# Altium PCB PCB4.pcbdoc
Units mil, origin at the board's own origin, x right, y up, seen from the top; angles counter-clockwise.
Board outline 10388.19 x 4173.23 mil, 4 copper layers (Top Layer, Inner1, Inner2, Bottom Layer); 12 components, 58 nets, 169 pads, 150 vias.
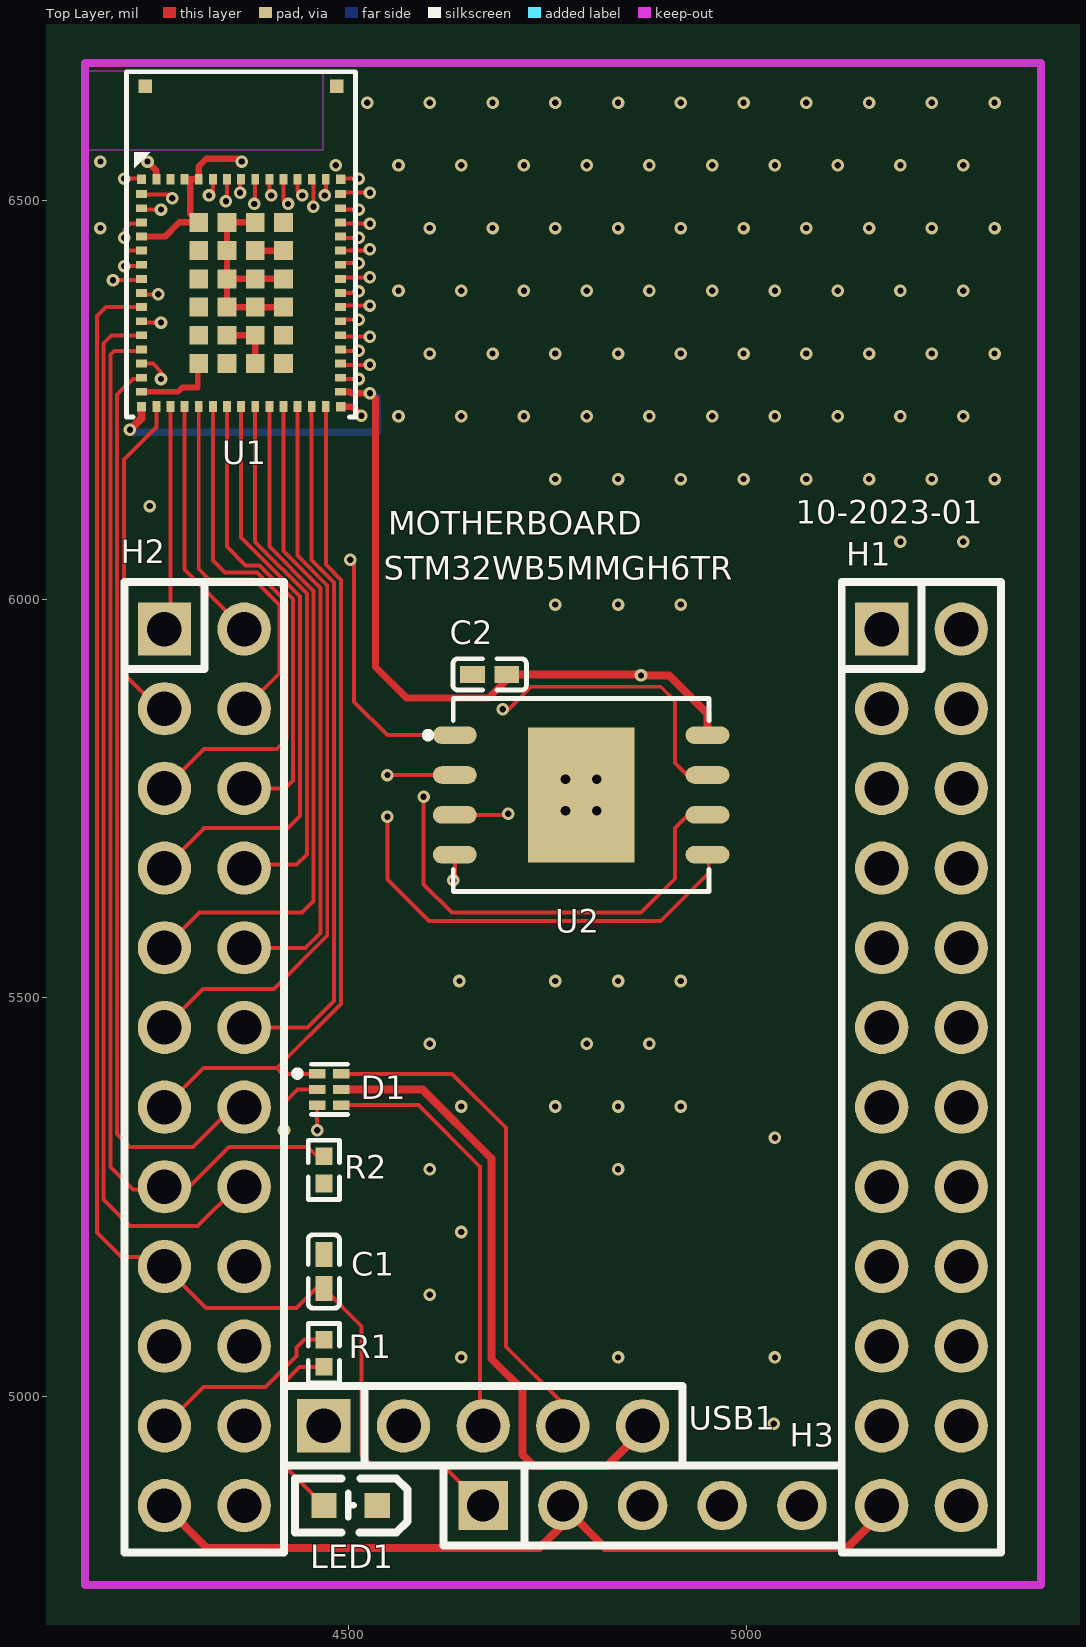
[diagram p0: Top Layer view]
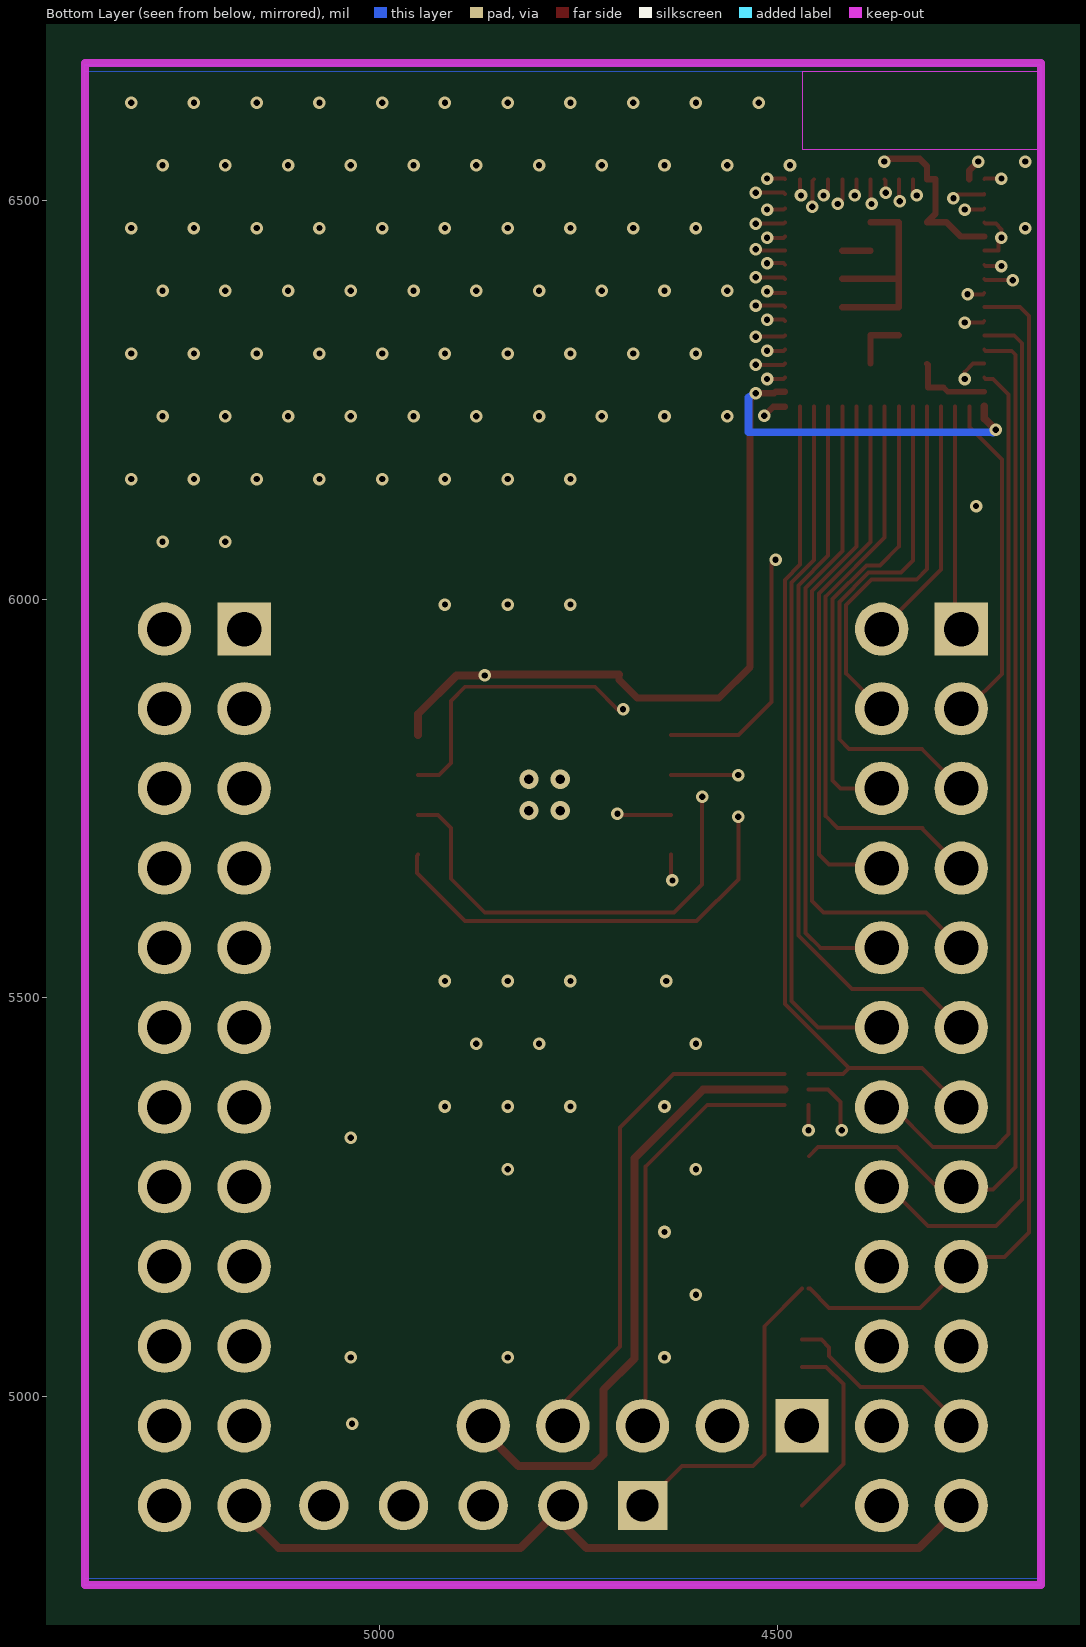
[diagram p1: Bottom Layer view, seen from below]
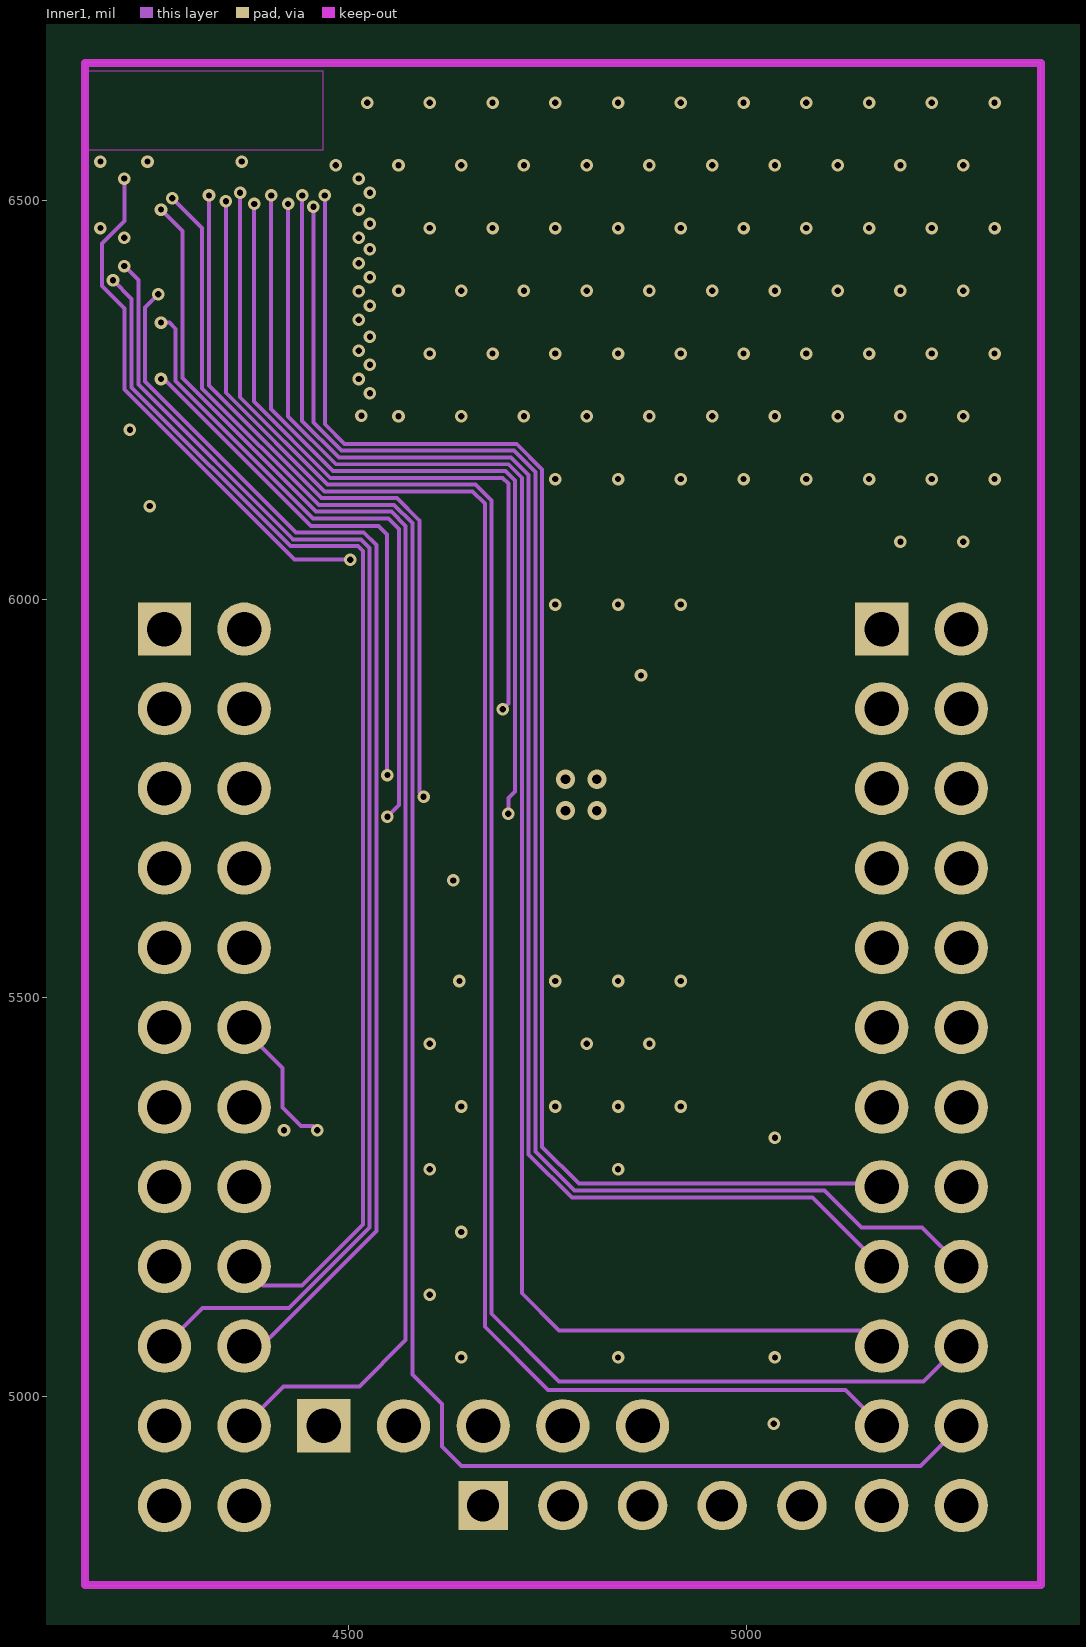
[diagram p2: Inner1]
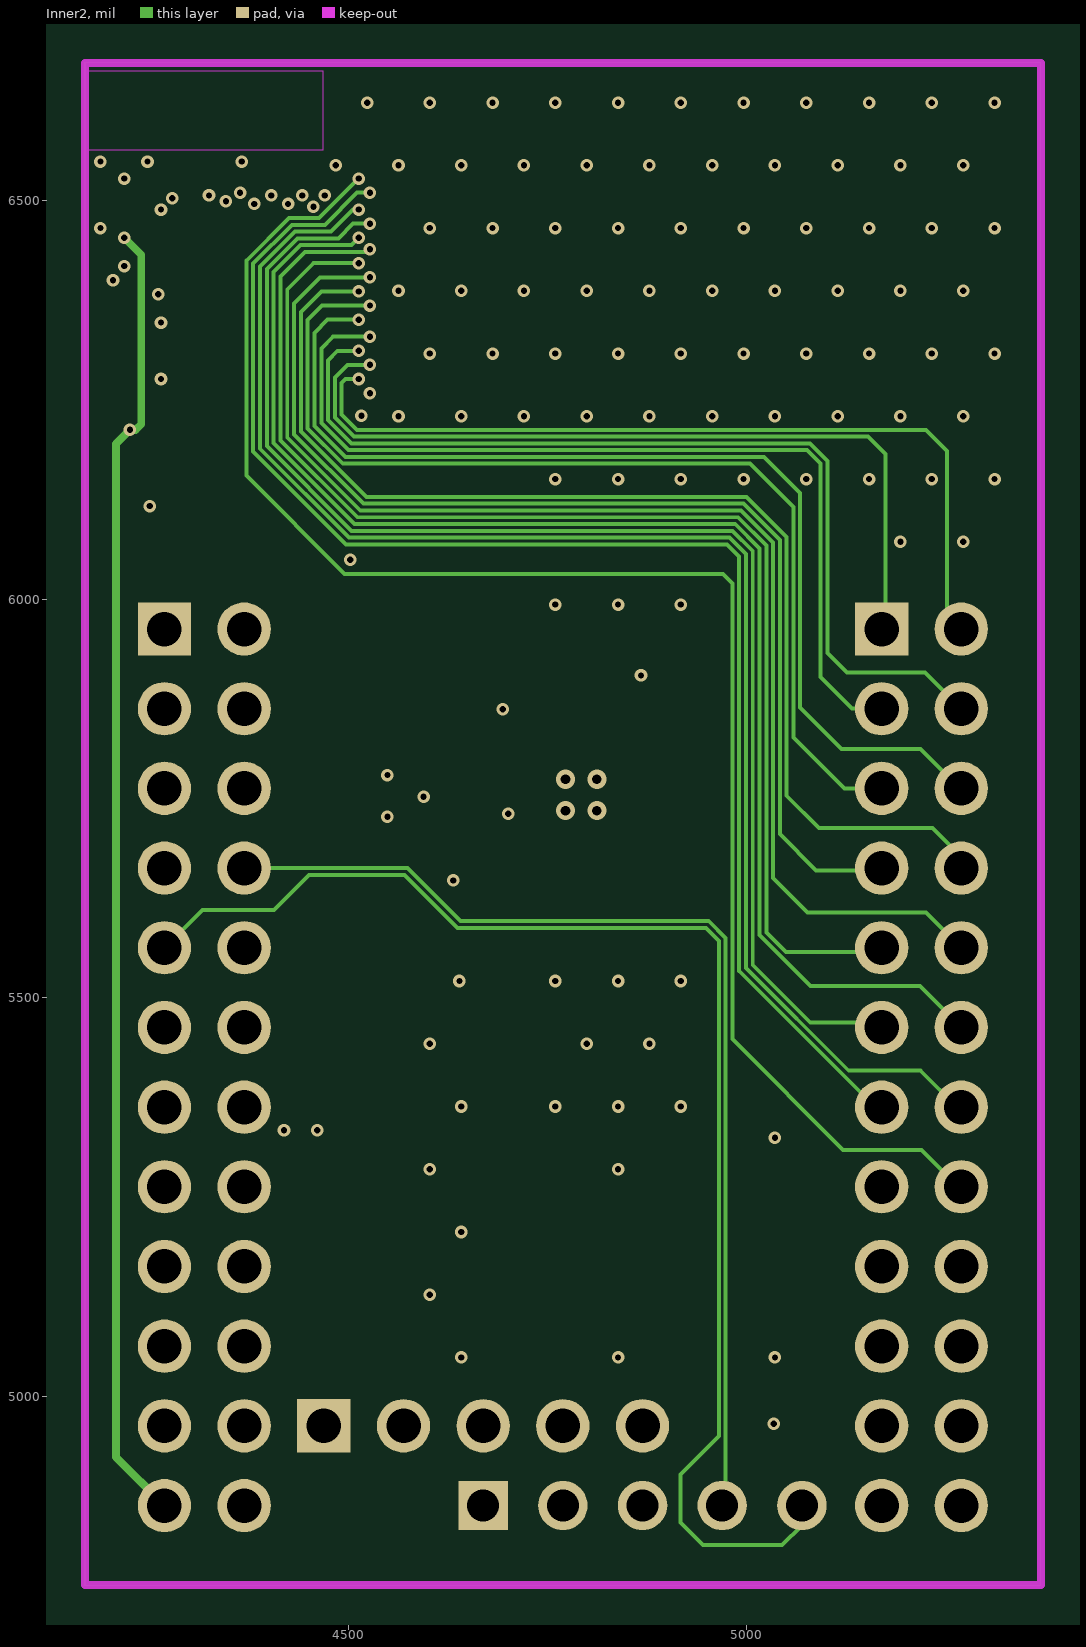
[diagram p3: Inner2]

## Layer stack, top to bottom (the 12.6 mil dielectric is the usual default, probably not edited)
Top Layer: signal copper (thickness not stored)
Dielectric: dielectric 12.6, FR-4, Dk 4.8
Inner1: signal copper (thickness not stored)
Dielectric: dielectric 12.6, FR-4, Dk 4.8
Inner2: signal copper (thickness not stored)
Dielectric: dielectric 12.6, FR-4, Dk 4.8
Bottom Layer: signal copper (thickness not stored)

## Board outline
13138.19,2750 2750,2750 2750,6923.23 13138.19,6923.23

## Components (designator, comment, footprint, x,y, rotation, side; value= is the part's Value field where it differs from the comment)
C1 "CL05B104KO5NNNC" C0402 4469.29,5156.3 r270 top
C2 "CL05B104KO5NNNC" C0402 4677.48,5905.69 r0 top
D1 "PRTR5V0U2F" SON-6_L1.5-W1.0-P0.50-BL 4476.17,5384.73 r270 top
H1 "PZ254-2-12-Z-8.5" HDR-TH_24P-P2.54-V-M-R2-C12-S2.54 5219.29,5412.6 r270 top
H2 "PZ254-2-12-Z-8.5" HDR-TH_24P-P2.54-V-M-R2-C12-S2.54 4319.29,5412.6 r270 top
H3 "HDR-F_2.54_1x5P" HDR-TH_5P-P2.54-V-F 4869.29,4862.6 r0 top
LED1 "19-217/R6C-AL1M2VY/3T" LED0603-R-RD 4502.79,4862.6 r180 top
R1 "0402WGJ0301TCE" R0402 4469.29,5053.73 r90 top
R2 "RC0402FR-0710KL" R0402 4469.29,5283.91 r90 top
U1 "STM32WB5MMGH6TR" LCC-LGA-86_L11.0-W7.3_STM32WB5MMGH6TR 4365.47,6442.6 r0 top
U2 "W25Q256JVEIQ_C97522" WSON-8_L8.0-W6.10-P1.27-BL-EP 4792.28,5754.38 r270 top
USB1 "HDR-M_2.54_1x5P" HDR-TH_5P-P2.54-V-M 4669.29,4962.6 r0 top

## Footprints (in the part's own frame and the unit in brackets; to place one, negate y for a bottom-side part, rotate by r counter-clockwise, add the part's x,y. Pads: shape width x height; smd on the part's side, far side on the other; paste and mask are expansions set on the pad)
C0402 [mm]
  rect 0.79x0.54 smd: 1(-0.545,0) 2(0.545,0)
  silkscreen extent -1.17,-0.5 1.17,0.5
HDR-TH_5P-P2.54-V-F [mil]
  rect 62x62 hole 40.16: 1(-200,0)
  round 62 hole 40.16: 2(-100,0) 3(0,0) 4(100,0) 5(200,0)
  silkscreen extent -250,-50 250,50
HDR-TH_5P-P2.54-V-M [mm]
  rect 1.7x1.7 hole 1.1: 1(-5.08,0)
  round 1.7 hole 1.1: 2(-2.54,0) 3(0,0) 4(2.54,0) 5(5.08,0)
  silkscreen extent -6.35,-1.27 6.35,1.27
HDR-TH_24P-P2.54-V-M-R2-C12-S2.54 [mm]
  rect 1.7x1.7 hole 1.1: 1(-13.97,-1.27)
  round 1.7 hole 1.1: 2(-13.97,1.27) 3(-11.43,-1.27) 4(-11.43,1.27) 5(-8.89,-1.27) 6(-8.89,1.27) 7(-6.35,-1.27) 8(-6.35,1.27) 9(-3.81,-1.27) 10(-3.81,1.27) 11(-1.27,-1.27) 12(-1.27,1.27) 13(1.27,-1.27) 14(1.27,1.27) 15(3.81,-1.27) 16(3.81,1.27) 17(6.35,-1.27) 18(6.35,1.27) 19(8.89,-1.27) 20(8.89,1.27) 21(11.43,-1.27) 22(11.43,1.27) 23(13.97,-1.27) 24(13.97,1.27)
  silkscreen extent -15.47,-2.54 15.47,2.54
LCC-LGA-86_L11.0-W7.3_STM32WB5MMGH6TR [mm]
  rect 0.3x0.3 smd: 1(-3.175,2.145) 17(-3.175,-5.105) 31(3.175,-5.105) 47(3.175,2.145)
  rect 0.35x0.25 smd: 2(-3.175,1.67) 3(-3.175,1.22) 4(-3.175,0.77) 5(-3.175,0.32) 6(-3.175,-0.13) 7(-3.175,-0.58) 8(-3.175,-1.03) 9(-3.175,-1.48) 10(-3.175,-1.93) 11(-3.175,-2.38) 12(-3.175,-2.83) 13(-3.175,-3.28) 14(-3.175,-3.73) 15(-3.175,-4.18) 16(-3.175,-4.63) 32(3.175,-4.63) 33(3.175,-4.18) 34(3.175,-3.73) 35(3.175,-3.28) 36(3.175,-2.83) 37(3.175,-2.38) 38(3.175,-1.93) 39(3.175,-1.48) 40(3.175,-1.03) 41(3.175,-0.58) 42(3.175,-0.13) 43(3.175,0.32) 44(3.175,0.77) 45(3.175,1.22) 46(3.175,1.67)
  rect 0.25x0.35 smd: 18(-2.7,-5.105) 19(-2.25,-5.105) 20(-1.8,-5.105) 21(-1.35,-5.105) 22(-0.9,-5.105) 23(-0.45,-5.105) 24(0,-5.105) 25(0.45,-5.105) 26(0.9,-5.105) 27(1.35,-5.105) 28(1.8,-5.105) 29(2.25,-5.105) 30(2.7,-5.105) 48(2.7,2.145) 49(2.25,2.145) 50(1.8,2.145) 51(1.35,2.145) 52(0.9,2.145) 53(0.45,2.145) 54(0,2.145) 55(-0.45,2.145) 56(-0.9,2.145) 57(-1.35,2.145) 58(-1.8,2.145) 59(-2.25,2.145) 60(-2.7,2.145)
  rect 0.6x0.6 smd: 61(-1.35,0.77) 62(-1.35,-0.13) 63(-1.35,-1.03) 64(-1.35,-1.93) 65(-1.35,-2.83) 66(-1.35,-3.73) 67(-0.45,-3.73) 68(0.45,-3.73) 69(1.35,-3.73) 70(1.35,-2.83) 71(1.35,-1.93) 72(1.35,-1.03) 73(1.35,-0.13) 74(1.35,0.77) 75(0.45,0.77) 76(-0.45,0.77) 77(-0.45,-0.13) 78(-0.45,-1.03) 79(-0.45,-1.93) 80(-0.45,-2.83) 81(0.45,-2.83) 82(0.45,-1.93) 83(0.45,-1.03) 84(0.45,-0.13)
  rect 0.43x0.43 smd: 85(-3.05,5.105) 86(3.05,5.105)
  silkscreen extent -3.65,-5.43 3.65,5.57
LED0603-R-RD [mm]
  rect 0.8x0.8 smd: 1(0.851,0) 2(-0.851,0)
  silkscreen extent -1.82,-0.86 1.77,0.86
R0402 [mm]
  rect 0.566x0.54 smd: 1(-0.433,0) 2(0.433,0)
  silkscreen extent -0.94,-0.5 0.94,0.5
SON-6_L1.5-W1.0-P0.50-BL [mm]
  rect 0.3x0.52 smd: 1(-0.5,-0.385) 2(0,-0.385) 3(0.5,-0.385) 4(0.5,0.385) 5(0,0.385) 6(-0.5,0.385)
  silkscreen extent -0.8,-1.12 0.8,0.58
WSON-8_L8.0-W6.10-P1.27-BL-EP [mm]
  oval 0.56x1.4 smd: 1(-1.905,-4.027) 2(-0.635,-4.027) 3(0.635,-4.027) 4(1.905,-4.027) 5(1.905,4.027) 6(0.635,4.027) 7(-0.635,4.027) 8(-1.905,4.027)
  rect 4.3x3.4 smd: 9(0,0)
  silkscreen extent -3.08,-4.98 3.08,4.08

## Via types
v1: diameter 15.75, hole 7.87, Top Layer to Bottom Layer, 146 vias
v2: diameter 24, hole 12, Top Layer to Bottom Layer, 4 vias

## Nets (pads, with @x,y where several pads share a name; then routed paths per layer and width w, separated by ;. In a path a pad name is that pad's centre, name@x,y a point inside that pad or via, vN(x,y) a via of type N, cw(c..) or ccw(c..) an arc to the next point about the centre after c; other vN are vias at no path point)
$1N994: LED1.1 R1.1 | length 234.9
  Top Layer w5: LED1.1 4417.32,4914.57 4417.32,5014.96 4439.05,5036.69 R1.1
BOOT0: H2.15 R2.2 U1.13 | length 1358.6
  Top Layer w5: U1.13 4238.82,6311.81 4206.44,6311.81 4201.44,6306.81 4201.44,5287.54 4229.53,5259.45 4266.14,5259.45 H2.15 4300,5262.6 4350,5312.6 4448.9,5312.6 R2.2@4460.54,5300.95
D+: D1.4 USB1.3 | length 532.5
  Top Layer w5: D1.4 4588.11,5365.05 4665.36,5287.8 4665.36,4966.54 USB1.3@4669.02,4962.88
D-: D1.6 USB1.4 | length 638.3
  Top Layer w5: D1.6 4630.23,5404.42 4697.62,5337.03 4697.62,5062.11 4769.29,4990.43 USB1.4
GND: C1.1 C2.1 D1.2 H1.24 H2.24 H3.3 LED1.2 R2.1 U1.5 U1.16 U1.31 U1.57 U1.58 U1.59 U1.60 U1.61 U1.62 U1.63 U1.64 U1.65 U1.66 U1.67 U1.68 U1.69 U1.70 U1.71 U1.72 U1.73 U1.74 U1.75 U1.76 U1.77 U1.78 U1.79 U1.80 U1.81 U1.82 U1.83 U1.84 U1.86 U2.4 U2.9 USB1.1 | length 890.4
  Top Layer w5: v1(4419.29,5333.72) 4420.87,5335.3 4420.87,5369.29 4436.31,5384.74 D1.2 ; v1(4631.8,5647.06) 4633.72,5648.98 U2.4
  Top Layer w7: U1.16 4286.22,6260.32 4291.65,6265.75 4311.02,6265.75 4311.02,6294.45 U1.66
  Top Layer w8: U1.5 4270.16,6455.2 4287.88,6472.92 U1.61 4301.69,6483.55 4301.69,6527.05 U1.57 4312.32,6543.43 4321.65,6552.76 4362.6,6552.76 v1(4366.14,6549.21) ; v1(4248.03,6549.21) 4259.17,6538.07 U1.60 ; U1.80 U1.81 U1.68 ; U1.84 U1.73 ; U1.75 U1.76 U1.77 U1.78 ; U1.71 U1.82 U1.79 U1.78 ; U1.72 U1.83 U1.78 ; U1.31 4505.24,6241.62 v1(4516.54,6230.32)
  other v1: 5033.86,4965.35 4641.73,5048.43 4838.58,5048.43 5035.43,5048.43 4602.36,5127.17 4641.73,5205.91 4602.36,5284.65 4838.58,5284.65 5035.43,5324.02 4641.73,5363.39 4759.84,5363.39 4838.58,5363.39 4917.32,5363.39 4602.36,5442.13 4799.21,5442.13 4877.95,5442.13 4639.47,5520.87 4759.84,5520.87 4838.58,5520.87 4917.32,5520.87 4759.84,5993.31 4838.58,5993.31 4917.32,5993.31 5192.91,6072.05 5271.65,6072.05 4250.79,6116.93 4759.84,6150.79 4838.58,6150.79 4917.32,6150.79 4996.06,6150.79 5074.8,6150.79 5153.54,6150.79 5232.28,6150.79 5311.02,6150.79 4562.99,6229.53 4641.73,6229.53 4720.47,6229.53 4799.21,6229.53 4877.95,6229.53 4956.69,6229.53 5035.43,6229.53 5114.17,6229.53 5192.91,6229.53 5271.65,6229.53 4602.36,6308.27 4681.1,6308.27 4759.84,6308.27 4838.58,6308.27 4917.32,6308.27 4996.06,6308.27 5074.8,6308.27 5153.54,6308.27 5232.28,6308.27 5311.02,6308.27 4562.99,6387.01 4641.73,6387.01 4720.47,6387.01 4799.21,6387.01 4877.95,6387.01 4956.69,6387.01 5035.43,6387.01 5114.17,6387.01 5192.91,6387.01 5271.65,6387.01 4188.98,6465.75 4602.36,6465.75 4681.1,6465.75 4759.84,6465.75 4838.58,6465.75 4917.32,6465.75 4996.06,6465.75 5074.8,6465.75 5153.54,6465.75 5232.28,6465.75 5311.02,6465.75 4484.25,6544.49 4562.99,6544.49 4641.73,6544.49 4720.47,6544.49 4799.21,6544.49 4877.95,6544.49 4956.69,6544.49 5035.43,6544.49 5114.17,6544.49 5192.91,6544.49 5271.65,6544.49 4188.98,6549.21 4523.62,6623.23 4602.36,6623.23 4681.1,6623.23 4759.84,6623.23 4838.58,6623.23 4917.32,6623.23 4996.06,6623.23 5074.8,6623.23 5153.54,6623.23 5232.28,6623.23 5311.02,6623.23
I2C1_SCL: H1.8 U1.39 | length 1510.7
  Top Layer w5: U1.39 4511.1,6384.33 v1(4512.99,6386.22)
  Inner2 w5: v1(4512.99,6386.22) 4466.17,6386.22 4440.47,6360.53 4440.47,6210.54 4522.64,6128.37 4999.77,6128.37 5050.16,6077.98 5050.16,5753.38 5090.55,5712.99 5233.07,5712.99 5269.29,5676.77 H1.8
I2C1_SDA: H2.3 U1.18 | length 421.1
  Top Layer w5: U1.18 4259.17,6216.05 4218.44,6175.32 4218.44,5906.37 4262.21,5862.6 H2.3
I2C3_SCL: H1.4 U1.35 | length 1227.4
  Top Layer w5: U1.35 4492.13,6311.81 v1(4512.99,6311.81)
  Inner2 w5: v1(4512.99,6311.81) 4486.74,6311.81 4474.65,6299.72 4474.65,6224.69 4503.74,6195.6 5079.21,6195.6 5101.18,6173.62 5101.18,5932.68 5125.99,5907.88 5224.02,5907.88 H1.4
I2C3_SDA: H1.6 U1.37 | length 1360.2
  Top Layer w5: U1.37 4492.36,6350.79 v1(4512.99,6350.79)
  Inner2 w5: v1(4512.99,6350.79) 4474.02,6350.79 4457.56,6334.33 4457.56,6217.61 4496.57,6178.6 5021.8,6178.6 5067.16,6133.23 5067.16,5863.94 5118.9,5812.21 5218.11,5812.21 5267.72,5762.6 H1.6
IO: USB1.2
LED: H2.21 R1.2 | length 251
  Top Layer w5: H2.21 4318.11,5011.42 4396.06,5011.42 4435.04,5050.39 4435.04,5061.02 4444.79,5070.77 R1.2
LPTIM1_IN1: H2.1 U1.19 | length 282.2
  Top Layer w5: H2.1 4276.89,5970.2 U1.19
LPTIM2_IN1: H2.16 U1.12 | length 1337
  Top Layer w5: U1.12 4202.84,6331.18 4192.89,6321.24 4192.89,5246.48 4225.99,5213.39 4311.02,5213.39 4360.24,5262.6 H2.16
LPUART1_RX: H1.16 U1.47 | length 2078.1
  Top Layer w5: U1.47 4491.38,6527.95 v1(4512.99,6527.95)
  Inner2 w5: v1(4512.99,6527.95) 4463.41,6478.37 4425.71,6478.37 4372.13,6424.79 4372.13,6155.04 4495.28,6031.89 4970.08,6031.89 4982.03,6019.94 4982.03,5448.01 5120.99,5309.06 5219.29,5309.06 5265.75,5262.6 H1.16
LPUART1_TX: H1.13 U1.46 | length 1890.8
  Top Layer w5: U1.46 4492.36,6510.24 v1(4527.17,6510.24)
  Inner2 w5: v1(4527.17,6510.24) 4511.03,6510.24 4470.62,6469.83 4429.25,6469.83 4380.67,6421.25 4380.67,6185.3 4497.19,6068.79 4975.15,6068.79 4990.53,6053.4 4990.53,5533.73 5161.94,5362.32 5169.01,5362.32 H1.13
NRST: C1.2 H2.17 H3.1 U1.10 | length 1943.8
  Top Layer w5: U1.10 4195.75,6366.62 4184.35,6355.22 4184.35,5205.41 4215.36,5174.41 4257.48,5174.41 H2.17 4321.26,5110.63 4435.04,5110.63 4459.25,5134.84 C1.2@4461.02,5134.84 ; C1.2 4516.54,5087.6 4516.54,4926.38 4530.71,4912.21 4619.69,4912.21 H3.1
PA0: H2.22 U1.3 | length 1873.8
  Top Layer w5: U1.3 4242.13,6488.98 v1(4264.96,6488.98)
  Inner1 w5: v1(4264.96,6488.98) 4291.89,6462.05 4291.89,6277.44 4459.46,6109.88 4554.08,6109.88 4572.07,6091.89 4572.07,5070.5 4513.78,5012.21 4418.9,5012.21 H2.22
PA1: H1.22 U1.2 | length 2485.5
  Top Layer w5: U1.2 4240.67,6508.15 4274.13,6508.15 v1(4279.13,6503.15)
  Inner1 w5: v1(4279.13,6503.15) 4316.7,6465.59 4316.7,6264.72 4463.04,6118.38 4557.6,6118.38 4580.57,6095.41 4580.57,5027.05 4617.73,4989.89 4617.73,4936.74 4642.27,4912.21 5218.11,4912.21 5268.51,4962.6 H1.22
PA8: H1.17 U1.50 | length 1971.8
  Top Layer w5: U1.50 4436.34,6512.48 v1(4442.13,6506.69)
  Inner1 w5: v1(4442.13,6506.69) 4442.13,6223.87 4488.11,6177.88 4704.38,6177.88 4726.31,6155.95 4726.31,5303.41 4780.5,5249.21 5082.82,5249.21 5169.29,5162.74 H1.17
PA15: H2.10 U1.27 | length 783
  Top Layer w5: H2.10 4446.25,5562.6 4465.04,5581.39 4465.04,6013.96 4418.62,6060.38 U1.27
PB0: H1.11 U1.44 | length 1790.4
  Top Layer w5: U1.44 4492.13,6471.26 v1(4527.17,6471.26)
  Inner2 w5: v1(4527.17,6471.26) 4505.91,6471.26 4487.47,6452.83 4436.42,6452.83 4397.76,6414.17 4397.76,6192.38 4504.31,6085.83 4982.15,6085.83 5007.58,6060.4 5007.58,5540.85 5079.92,5468.5 5163.39,5468.5 H1.11
PB1: H1.12 U1.43 | length 1813.5
  Top Layer w5: U1.43 4492.13,6453.55 v1(4512.99,6453.55)
  Inner2 w5: v1(4512.99,6453.55) 4503.78,6444.33 4440,6444.33 4406.3,6410.63 4406.3,6195.92 4507.84,6094.37 4985.62,6094.37 5016.12,6063.88 5016.12,5578.37 5079.92,5514.57 5217.32,5514.57 H1.12
PB2: H1.15 U1.48 | length 1901.3
  Top Layer w5: v1(4470.47,6506.69) 4471.77,6507.99 U1.48
  Inner1 w5: v1(4470.47,6506.69) 4470.47,6219.69 4495.28,6194.88 4711.42,6194.88 4743.31,6162.99 4743.31,5312.6 4789.37,5266.54 5165.36,5266.54 H1.15
PB12: H1.10 U1.41 | length 1670
  Top Layer w5: U1.41 4492.36,6421.66 v1(4512.99,6421.66)
  Inner2 w5: v1(4512.99,6421.66) 4456.3,6421.66 4423.39,6388.74 4423.39,6202.99 4515.01,6111.37 4992.66,6111.37 5033.12,6070.92 ; 5033.12,6070.87 5033.12,5649.95 5076.38,5606.69 5225.2,5606.69 H1.10
PB15: H1.5 U1.38 | length 1336.2
  Top Layer w5: U1.38 4492.36,6368.51 v1(4527.17,6368.51)
  Inner2 w5: v1(4527.17,6368.51) 4466.93,6368.51 4449.02,6350.59 4449.02,6214.07 4493.04,6170.06 5004.15,6170.06 5058.66,6115.54 5058.66,5826.38 5122.44,5762.6 H1.5
PC1: H2.20 U1.9 | length 1600.8
  Top Layer w5: U1.9 4242.13,6382.68 v1(4261.42,6382.68)
  Inner1 w5: v1(4261.42,6382.68) 4245.12,6366.38 4245.12,6273 4434.49,6083.63 4519.4,6083.63 4535.2,6067.83 4535.2,5207.25 4388.98,5061.02 4370.87,5061.02 H2.20
PC4: H1.18 U1.49 | length 2057.3
  Top Layer w5: U1.49 4456.3,6524.8 v1(4456.3,6492.52)
  Inner1 w5: v1(4456.3,6492.52) 4456.3,6221.78 4491.69,6186.38 4707.9,6186.38 4734.81,6159.47 4734.81,5306.93 4784.02,5257.71 5097.74,5257.71 5143.81,5211.65 5220.24,5211.65 H1.18
PC5: H1.14 U1.45 | length 1932.1
  Top Layer w5: U1.45 4492.13,6488.98 v1(4512.99,6488.98)
  Inner2 w5: v1(4512.99,6488.98) 4505.92,6488.98 4478.27,6461.33 4432.83,6461.33 4389.21,6417.71 4389.21,6188.84 4500.77,6077.29 4978.67,6077.29 4999.03,6056.92 4999.03,5537.31 5128.08,5408.27 5218.11,5408.27 5263.78,5362.6 H1.14
PC6: H1.3 U1.36 | length 1206.7
  Top Layer w5: U1.36 4492.13,6329.53 v1(4527.17,6329.53)
  Inner2 w5: v1(4527.17,6329.53) 4481.1,6329.53 4466.1,6314.53 4466.1,6221.15 4500.16,6187.1 5075.69,6187.1 5092.68,6170.1 5092.68,5902.2 5132.28,5862.6 H1.3
PC10: H2.5 U1.22 | length 657.8
  Top Layer w5: H2.5 4318.9,5812.21 4410.24,5812.21 4422.32,5824.29 4422.32,5996.45 4385.47,6033.3 4345.04,6033.3 4330.04,6048.31 U1.22
PC11: H2.6 U1.23 | length 579.2
  Top Layer w5: U1.23 4347.76,6066.03 4371.26,6042.52 4388.34,6042.52 4430.87,5999.99 4430.87,5772.6 4420.87,5762.6 H2.6
PC12: H2.7 U1.24 | length 742.4
  Top Layer w5: H2.7 4318.11,5711.42 4318.11,5712.99 4424.41,5712.99 4439.41,5727.99 4439.41,6003.53 4365.47,6077.47 U1.24
PC13: H1.7 U1.40 | length 1491.9
  Top Layer w5: U1.40 4492.36,6403.94 v1(4527.17,6403.94)
  Inner2 w5: v1(4527.17,6403.94) 4464.78,6403.94 4431.93,6371.09 4431.93,6207 4519.06,6119.87 4996.25,6119.87 5041.66,6074.46 5041.66,5705.19 5087.01,5659.84 5166.54,5659.84 H1.7
PE4: H1.9 U1.42 | length 1676.8
  Top Layer w5: U1.42 4525.28,6437.48 v1(4527.17,6439.37)
  Inner2 w5: v1(4527.17,6439.37) 4523.62,6435.83 4445.67,6435.83 4414.84,6405 4414.84,6199.45 4511.43,6102.87 4989.14,6102.87 5024.62,6067.4 5024.62,5581.89 5049.42,5557.09 5163.78,5557.09 H1.9
QSPI_CLK: U1.56 U2.6 | length 1513.1
  Top Layer w5: v1(4325.2,6506.69) 4330.04,6511.54 U1.56 ; v1(4594.49,5751.97) 4594.49,5642.13 4629.92,5606.69 4867.32,5606.69 4909.84,5649.21 4909.84,5712.99 4926.23,5729.38 U2.6
  Inner1 w5: v1(4325.2,6506.69) 4325.2,6268.31 4466.62,6126.88 4561.19,6126.88 4589.07,6099 4589.07,5757.39 v1(4594.49,5751.97)
QSPI_CS: U1.1 U2.1 | length 1006.3
  Top Layer w5: v1(4218.9,6527.95) 4239.57,6527.95 U1.1 ; v1(4502.36,6049.61) 4507.36,6044.61 4507.36,5870.99 4548.97,5829.38 U2.1
  Inner1 w5: v1(4218.9,6527.95) 4218.9,6474.81 4190.81,6446.71 4190.81,6393.05 4218.9,6364.96 4218.9,6262.97 4432.26,6049.61 v1(4502.36,6049.61)
QSPI_IO0: U1.11 U2.5 | length 1388.8
  Top Layer w5: U1.11 4242.13,6347.25 v1(4264.96,6347.25) ; v1(4549.12,5727.17) 4549.12,5648.52 4601.58,5596.06 4892.13,5596.06 4952.36,5656.3 4952.36,5677.85 U2.5
  Inner1 w5: v1(4264.96,6347.25) 4275.59,6347.25 4283.39,6339.44 4283.39,6273.86 4455.92,6101.34 4550.54,6101.34 4563.53,6088.36 4563.53,5741.58 v1(4549.12,5727.17)
QSPI_IO1: U1.14 U2.2 | length 789
  Top Layer w5: U1.14 4254.65,6295.75 4264.96,6285.44 v1(4264.96,6276.38) ; v1(4549.12,5779.38) U2.2
  Inner1 w5: v1(4264.96,6276.38) 4268.8,6276.38 4453.05,6092.13 4537.8,6092.13 4548.43,6081.5 4548.43,5780.07 v1(4549.12,5779.38)
QSPI_IO2: U1.52 U2.3 | length 1122
  Top Layer w5: U1.52 4400.91,6508.94 v1(4403.15,6506.69) ; U2.3 4699.46,5729.38 v1(4700.79,5730.71)
  Inner1 w5: v1(4403.15,6506.69) 4403.15,6238.68 4480.95,6160.88 4697.34,6160.88 4709.31,6148.91 4709.31,5758.81 4700.79,5750.29 v1(4700.79,5730.71)
QSPI_IO3: U1.53 U2.7 | length 1288
  Top Layer w5: v1(4381.89,6496.06) 4383.19,6497.36 U1.53 ; v1(4693.7,5861.81) 4700.79,5861.81 4729.14,5890.16 4892.13,5890.16 4909.84,5872.44 4909.84,5794.49 4924.96,5779.38 U2.7
  Inner1 w5: v1(4381.89,6496.06) 4381.89,6247.86 4477.37,6152.38 4693.81,6152.38 4700.81,6145.39 4700.81,5868.92 v1(4693.7,5861.81)
SPI1_CS: H1.21 U1.55 | length 2233.6
  Top Layer w5: v1(4346.46,6499.61) 4347.76,6500.91 U1.55
  Inner1 w5: v1(4346.46,6499.61) 4346.46,6259.13 4470.2,6135.38 4656.14,6135.38 4671.28,6120.24 4671.28,5086.98 4750.4,5007.87 5124.02,5007.87 H1.21
SPI1_SCK: H1.20 U1.54 | length 2306.8
  Top Layer w5: v1(4364.17,6510.24) 4364.17,6525.75 U1.54
  Inner1 w5: v1(4364.17,6510.24) 4364.17,6253.49 4473.78,6143.88 4659.66,6143.88 4679.78,6123.76 4679.78,5103.29 4764.57,5018.5 5221.66,5018.5 5265.75,5062.6 H1.20
SPI2_CS: H1.2 U1.33 | length 1070.8
  Top Layer w5: U1.33 4492.13,6276.38 v1(4512.99,6276.38)
  Inner2 w5: v1(4512.99,6276.38) 4496.73,6276.38 4491.73,6271.38 4491.73,6231.77 4510.91,6212.6 5225.2,6212.6 5251.58,6186.22 H1.2@5251.58,5980.32
SPI2_MISO: H2.18 U1.8 | length 1591.6
  Top Layer w5: v1(4204.73,6400.4) 4238.82,6400.4 U1.8
  Inner1 w5: v1(4204.73,6400.4) 4228.12,6377.01 4228.12,6265.84 4427.32,6066.63 4512.3,6066.63 4518.2,6060.72 4518.2,5215.05 4442.13,5138.98 4392.92,5138.98 H2.18
SPI2_MOSI: H2.19 U1.7 | length 1725.2
  Top Layer w5: v1(4218.9,6418.11) 4238.82,6418.11 U1.7
  Inner1 w5: v1(4218.9,6418.11) 4236.62,6400.4 4236.62,6269.42 4430.91,6075.13 4515.82,6075.13 4526.7,6064.25 4526.7,5211.47 4425.86,5110.63 4317.32,5110.63 H2.19
SPI2_SCK: H1.1 U1.34 | length 1069.8
  Top Layer w5: U1.34 4492.13,6294.1 v1(4527.17,6294.1)
  Inner2 w5: v1(4527.17,6294.1) 4498.82,6294.1 4483.19,6278.47 4483.19,6228.23 4507.32,6204.1 5152.2,6204.1 5174.29,6182.01 5174.29,5967.6 H1.1
SWDCK: H2.9 H3.5 U1.26 | length 2572
  Top Layer w5: H2.9 4313.39,5606.69 4442.13,5606.69 4456.5,5621.06 4456.5,6010.49 4400.91,6066.08 U1.26
  Inner2 w5: H2.9 4316.93,5610.24 4406.69,5610.24 4450.56,5654.1 4570.5,5654.1 4637.03,5587.56 4948.78,5587.56 4965.03,5571.31 4965.03,4949.68 4916.93,4901.58 4916.93,4841.34 4945.28,4812.99 5044.49,4812.99 5069.29,4837.8 H3.5
SWDIO: H2.8 H3.4 U1.25 | length 2029
  Top Layer w5: H2.8 4373.62,5666.93 4435.04,5666.93 4447.95,5679.84 4447.95,6007.01 4383.19,6071.77 U1.25
  Inner2 w5: H2.8 4574.02,5662.6 4640.55,5596.06 4952.36,5596.06 4973.53,5574.89 4973.53,4866.84 H3.4
USART1_CTS: H2.2 U1.20 | length 310
  Top Layer w5: U1.20 4294.61,6037.29 H2.2
USART1_RTS: H2.4 U1.21 | length 472.7
  Top Layer w5: U1.21 4312.32,6037.68 4325.2,6024.8 4381.89,6024.8 4413.78,5992.91 4413.78,5907.09 H2.4
USART1_RX: H2.11 U1.28 | length 931.2
  Top Layer w5: H2.11 4317.72,5511.02 4406.69,5511.02 4473.58,5577.91 4473.58,6017.44 4436.34,6054.69 U1.28
USART1_TX: H1.19 U1.51 | length 2127.7
  Top Layer w5: U1.51 4418.62,6501.85 v1(4424.41,6496.06)
  Inner1 w5: v1(4424.41,6496.06) 4424.41,6229.5 4484.53,6169.38 4700.86,6169.38 4717.81,6152.43 4717.81,5129.04 4764.57,5082.28 5149.61,5082.28 H1.19
USBN: D1.1 H2.13 U1.30 | length 1086.1
  Top Layer w5: H2.13 4318.5,5411.81 4410.24,5411.81 ; D1.1 4417.63,5404.42 4410.24,5411.81 ; U1.30 4471.77,6043.29 4490.67,6024.4 4490.67,5492.24 4410.24,5411.81
USBP: D1.3 H2.12 U1.29 | length 1091.2
  Top Layer w5: H2.12 4449.01,5462.6 4482.13,5495.72 4482.13,6020.92 4454.06,6048.99 U1.29 ; v1(4461.01,5333.72) D1.3
  Inner1 w5: H2.12 4369.29,5459.84 4417.32,5411.81 4417.32,5362.21 4440.81,5338.72 4456.01,5338.72 v1(4461.01,5333.72)
VBAT: H2.14 U1.15 | length 1140.1
  Top Layer w5: U1.15 4238.82,6276.38 4229.53,6276.38 4209.89,6256.75 4209.89,5328.69 4225.99,5312.6 4305.12,5312.6 H2.14@4355.12,5362.6
VBUS: D1.5 USB1.5 | length 793.1
  Top Layer w10: D1.5 4593.22,5384.74 4679.53,5298.43 4679.53,5046.85 4718.51,5007.87 4718.51,4926.38 4732.68,4912.21 4824.8,4912.21 4869.29,4956.69 USB1.5
VCC: C2.2 H1.23 H2.23 H3.2 U1.4 U1.6 U1.17 U1.32 U2.8 | length 4003
  Top Layer w5: U1.6 4222.44,6437.48 4222.44,6450 v1(4218.9,6453.55) 4218.9,6464.18 4225.99,6471.26 4238.82,6471.26 U1.4
  Top Layer w8: U1.32 4502.36,6260.32 4504.02,6258.66 v1(4527.17,6258.66)
  Top Layer w9: v1(4527.17,6258.66) 4534.25,6251.58 4534.25,5914.96 4573.23,5875.99 4675.99,5875.99 4698.94,5898.94 C2.2
  Top Layer w10: v1(4225.99,6212.6) 4240.47,6227.09 U1.17 ; H2.23 4322.44,4809.45 4739.77,4809.45 4769.29,4838.98 H3.2 4822.44,4809.45 5125.99,4809.45 5169.29,4852.76 H1.23 ; C2.2 4865.96,5905.69 v1(4867.32,5904.33) 4902.73,5904.33 4950.84,5856.22 U2.8
  Inner2 w10: v1(4218.9,6453.55) 4240.16,6432.29 4240.16,6219.69 4233.07,6212.6 v1(4225.99,6212.6) 4208.27,6194.88 4208.27,4923.62 H2.23
  Bottom Layer w10: v1(4225.99,6212.6) 4229.53,6209.06 4536.4,6209.6 4536.32,6253.25 v1(4527.17,6258.66)
"": U1.85
  other v2: 4772.59,5734.69 4811.96,5734.69 4772.59,5774.06 4811.96,5774.06

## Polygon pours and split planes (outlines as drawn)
GND on Bottom Layer (solid, remove dead copper, pour order 0): 4169.29,4762.6 5369.29,4762.6 5369.29,6662.6 4169.29,6662.6
GND on Bottom Layer (solid, remove dead copper, pour order 1): 4169.29,4770.9 5369.29,4770.9 5369.29,6670.9 4169.29,6670.9
GND on Bottom Layer (solid, remove dead copper, pour order 2): 4169.29,4762.6 5369.29,4762.6 5369.29,6662.6 4169.29,6662.6
GND on Top Layer (solid, remove dead copper, pour order 3): 4169.29,4762.6 5369.29,4762.6 5369.29,6673.23 4169.29,6673.23
GND on Inner2 (solid, remove dead copper, pour order 4): 4169.29,4762.6 5369.29,4762.6 5369.29,6673.23 4169.29,6673.23
GND on Inner1 (solid, remove dead copper, pour order 5): 4169.29,4762.6 5369.29,4762.6 5369.29,6673.23 4169.29,6673.23

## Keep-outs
Board Outline Layer:
  lines w10 net "": 4169.29,4762.6 5369.29,4762.6 5369.29,6673.23 4169.29,6673.23 4169.29,4762.6
Multi-Layer:
  region net "": 4169.29,6564.18 4468.5,6564.18 4468.5,6662.6 4169.29,6662.6

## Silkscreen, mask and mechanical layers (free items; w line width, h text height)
Top Silkscreen Layer:
  text "10-2023-01" at 5061.37,6095.03 h29.2
  text "MOTHERBOARD" at 4549.85,6080.86 h29.2
  text "STM32WB5MMGH6TR" at 4544.72,6024.16 h29.2
Mech6:
  text "SPI2_SCK/SPI2CS /  PC6/I2C3_SCL /  PB15/I2C3_SDA /  PC13/I2C1_SCL /  PE4/PB12 /  PB0/PB1 /  LPUART1_TX/PC5 /  PB2/LPUART1_RX /  PA8/PC4 /  USART1_TX/SPI1_SCK /  SPI1_CS/PA1 /  VCC/GND" at 5228.04,4835.19 h77.56
  text "LPTIM1_IN1/USART1_CTS /  I2C1_SDA/USART1_RTS /  PC10/PC11 /  PC12/SWDIO /  SWDCK/PA15 /  USART1_RX/USBP /  USBN/VBAT /  BOOT0/LPTIM2_IN1 /  NRST/SPI2_MISO /  SPI2_MOSI/PC1 /  LED/PA0 /  VCC/GND" at 2812.31,4821.02 h77.56
  text "USB VBUS /  D- /  D+ /  IO /  GND" at 4411.18,4791.01 h76.18 r270
  text "SWDCK /  SWDIO /  GND /  VCC /  NRST" at 4627.32,4237.58 h76.18 r270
